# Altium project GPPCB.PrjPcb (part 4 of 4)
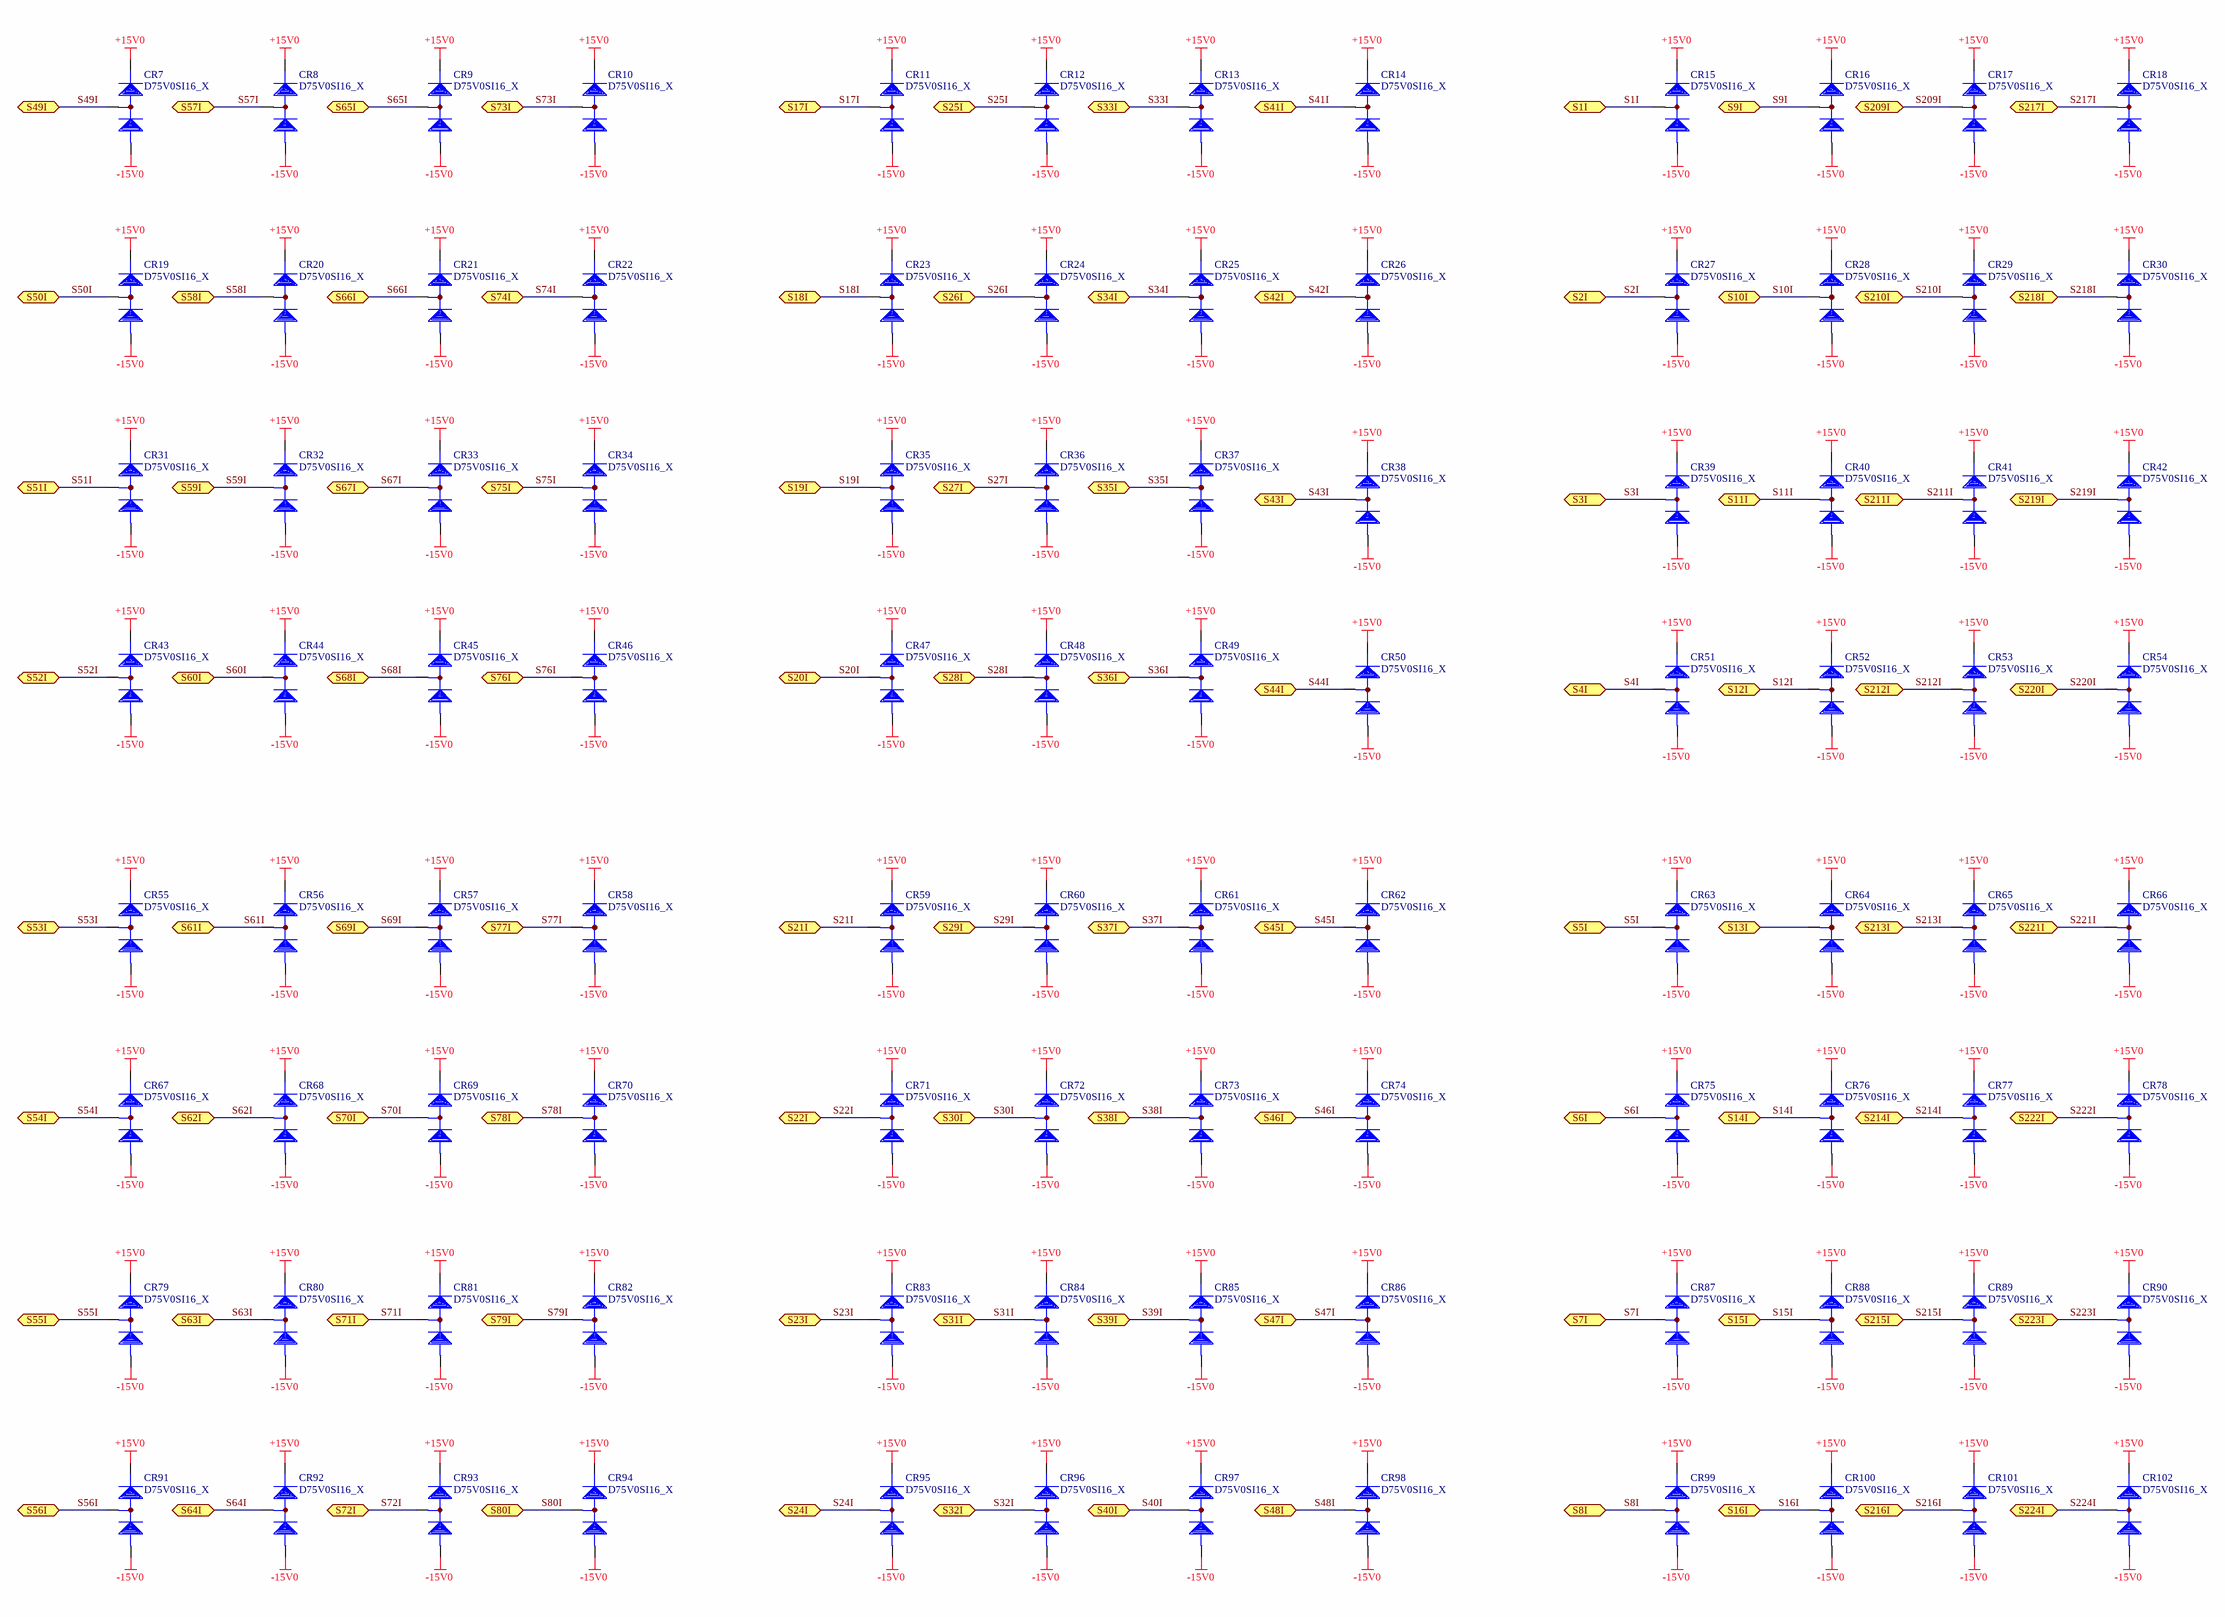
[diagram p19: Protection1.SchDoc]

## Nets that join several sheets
+5V0: 15 and 5 Volts (12 pins), ByPass (77 pins), Controller (7 pins), Decoder (9 pins), Latch1 (8 pins), Latch2 (8 pins), Latch3 (8 pins), Latch4 (8 pins), Latch5 (8 pins), Latch6 (8 pins), Latch7 (8 pins)
+15V0: 15 and 5 Volts (12 pins), Protection (128 pins), Protection1 (96 pins)
-5V0: 15 and 5 Volts (7 pins), ByPass (48 pins), Latch1 (7 pins), Latch2 (8 pins), Latch3 (8 pins), Latch4 (8 pins), Latch5 (8 pins), Latch6 (8 pins), Latch7 (8 pins)
-15V0: 15 and 5 Volts (7 pins), Protection (128 pins), Protection1 (96 pins)
DGND: 15 and 5 Volts (46 pins), 28 PowerSupply (8 pins)
GND: 28 PowerSupply (P1.3), ByPass (125 pins), Controller (15 pins), Decoder (9 pins), Latch1 (8 pins), Latch2 (8 pins), Latch3 (8 pins), Latch4 (8 pins), Latch5 (8 pins), Latch6 (8 pins), Latch7 (8 pins)
D0: Controller (U5.33), Latch1 (U16.3 U17.3 U22.3 U23.3), Latch2 (U28.3 U29.3 U34.3 U35.3), Latch3 (U40.3 U41.3 U46.3 U47.3), Latch4 (U52.3 U53.3 U58.3 U59.3), Latch5 (U64.3 U65.3 U70.3 U71.3), Latch6 (U76.3 U77.3 U82.3 U83.3), Latch7 (U88.3 U89.3 U94.3 U95.3)
D1: Controller (U5.34), Latch1 (U16.4 U17.4 U22.4 U23.4), Latch2 (U28.4 U29.4 U34.4 U35.4), Latch3 (U40.4 U41.4 U46.4 U47.4), Latch4 (U52.4 U53.4 U58.4 U59.4), Latch5 (U64.4 U65.4 U70.4 U71.4), Latch6 (U76.4 U77.4 U82.4 U83.4), Latch7 (U88.4 U89.4 U94.4 U95.4)
D2: Controller (U5.35), Latch1 (U16.7 U17.7 U22.7 U23.7), Latch2 (U28.7 U29.7 U34.7 U35.7), Latch3 (U40.7 U41.7 U46.7 U47.7), Latch4 (U52.7 U53.7 U58.7 U59.7), Latch5 (U64.7 U65.7 U70.7 U71.7), Latch6 (U76.7 U77.7 U82.7 U83.7), Latch7 (U88.7 U89.7 U94.7 U95.7)
D3: Controller (U5.36), Latch1 (U16.8 U17.8 U22.8 U23.8), Latch2 (U28.8 U29.8 U34.8 U35.8), Latch3 (U40.8 U41.8 U46.8 U47.8), Latch4 (U52.8 U53.8 U58.8 U59.8), Latch5 (U64.8 U65.8 U70.8 U71.8), Latch6 (U76.8 U77.8 U82.8 U83.8), Latch7 (U88.8 U89.8 U94.8 U95.8)
D4: Controller (U5.37), Latch1 (U16.13 U17.13 U22.13 U23.13), Latch2 (U28.13 U29.13 U34.13 U35.13), Latch3 (U40.13 U41.13 U46.13 U47.13), Latch4 (U52.13 U53.13 U58.13 U59.13), Latch5 (U64.13 U65.13 U70.13 U71.13), Latch6 (U76.13 U77.13 U82.13 U83.13), Latch7 (U88.13 U89.13 U94.13 U95.13)
D5: Controller (U5.38), Latch1 (U16.14 U17.14 U22.14 U23.14), Latch2 (U28.14 U29.14 U34.14 U35.14), Latch3 (U40.14 U41.14 U46.14 U47.14), Latch4 (U52.14 U53.14 U58.14 U59.14), Latch5 (U64.14 U65.14 U70.14 U71.14), Latch6 (U76.14 U77.14 U82.14 U83.14), Latch7 (U88.14 U89.14 U94.14 U95.14)
D6: Controller (U5.39), Latch1 (U16.17 U17.17 U22.17 U23.17), Latch2 (U28.17 U29.17 U34.17 U35.17), Latch3 (U40.17 U41.17 U46.17 U47.17), Latch4 (U52.17 U53.17 U58.17 U59.17), Latch5 (U64.17 U65.17 U70.17 U71.17), Latch6 (U76.17 U77.17 U82.17 U83.17), Latch7 (U88.17 U89.17 U94.17 U95.17)
D7: Controller (U5.40), Latch1 (U16.18 U17.18 U22.18 U23.18), Latch2 (U28.18 U29.18 U34.18 U35.18), Latch3 (U40.18 U41.18 U46.18 U47.18), Latch4 (U52.18 U53.18 U58.18 U59.18), Latch5 (U64.18 U65.18 U70.18 U71.18), Latch6 (U76.18 U77.18 U82.18 U83.18), Latch7 (U88.18 U89.18 U94.18 U95.18)
DLE1: Controller (U5.27), Decoder (8 pins)
DLE2: Controller (U5.28), Decoder (8 pins)
DLE3: Controller (U5.29), Decoder (8 pins)
LE1: Decoder (U8.15), Latch1 (U16.11)
LE2: Decoder (U8.14), Latch1 (U22.11)
LE3: Decoder (U8.13), Latch1 (U17.11)
LE4: Decoder (U8.12), Latch1 (U23.11)
LE5: Decoder (U8.11), Latch2 (U28.11)
LE6: Decoder (U8.10), Latch2 (U34.11)
LE7: Decoder (U8.9), Latch2 (U29.11)
LE8: Decoder (U8.7), Latch2 (U35.11)
LE9: Decoder (U9.15), Latch3 (U40.11)
LE10: Decoder (U9.14), Latch3 (U46.11)
LE11: Decoder (U9.13), Latch3 (U41.11)
LE12: Decoder (U9.12), Latch3 (U47.11)
LE13: Decoder (U9.11), Latch4 (U52.11)
LE14: Decoder (U9.10), Latch4 (U58.11)
LE15: Decoder (U9.9), Latch4 (U53.11)
LE16: Decoder (U9.7), Latch4 (U59.11)
LE17: Decoder (U10.15), Latch5 (U64.11)
LE18: Decoder (U10.14), Latch5 (U70.11)
LE19: Decoder (U10.13), Latch5 (U65.11)
LE20: Decoder (U10.12), Latch5 (U71.11)
LE21: Decoder (U10.11), Latch6 (U76.11)
LE22: Decoder (U10.10), Latch6 (U82.11)
LE23: Decoder (U10.9), Latch6 (U77.11)
LE24: Decoder (U10.7), Latch6 (U83.11)
LE25: Decoder (U7.15), Latch7 (U88.11)
LE26: Decoder (U7.14), Latch7 (U94.11)
LE27: Decoder (U7.13), Latch7 (U89.11)
LE28: Decoder (U7.12), Latch7 (U95.11)
LOE1: Decoder (U13.15), Latch1 (U16.1)
LOE2: Decoder (U13.14), Latch1 (U22.1)
LOE3: Decoder (U13.13), Latch1 (U17.1)
LOE4: Decoder (U13.12), Latch1 (U23.1)
LOE5: Decoder (U13.11), Latch2 (U28.1)
LOE6: Decoder (U13.10), Latch2 (U34.1)
LOE7: Decoder (U13.9), Latch2 (U29.1)
LOE8: Decoder (U13.7), Latch2 (U35.1)
LOE9: Decoder (U14.15), Latch3 (U40.1)
LOE10: Decoder (U14.14), Latch3 (U46.1)
LOE11: Decoder (U14.13), Latch3 (U41.1)
LOE12: Decoder (U14.12), Latch3 (U47.1)
LOE13: Decoder (U14.11), Latch4 (U52.1)
LOE14: Decoder (U14.10), Latch4 (U58.1)
LOE15: Decoder (U14.9), Latch4 (U53.1)
LOE16: Decoder (U14.7), Latch4 (U59.1)
LOE17: Decoder (U15.15), Latch5 (U64.1)
LOE18: Decoder (U15.14), Latch5 (U70.1)
LOE19: Decoder (U15.13), Latch5 (U65.1)
LOE20: Decoder (U15.12), Latch5 (U71.1)
LOE21: Decoder (U15.11), Latch6 (U76.1)
LOE22: Decoder (U15.10), Latch6 (U82.1)
LOE23: Decoder (U15.9), Latch6 (U77.1)
LOE24: Decoder (U15.7), Latch6 (U83.1)
LOE25: Decoder (U12.15), Latch7 (U88.1)
LOE26: Decoder (U12.14), Latch7 (U94.1)
LOE27: Decoder (U12.13), Latch7 (U89.1)
LOE28: Decoder (U12.12), Latch7 (U95.1)
S1I: Connector (J1.1), Latch1 (U27.3), Protection1 (CR15.3)
S1O: Connector (J1.17), Latch1 (U27.2)
S2I: Connector (J1.2), Latch1 (U27.14), Protection1 (CR27.3)
S2O: Connector (J1.18), Latch1 (U27.15)
S3I: Connector (J1.3), Latch1 (U27.11), Protection1 (CR39.3)
S3O: Connector (J1.19), Latch1 (U27.10)
S4I: Connector (J1.4), Latch1 (U27.6), Protection1 (CR51.3)
S4O: Connector (J1.20), Latch1 (U27.7)
S5I: Connector (J1.5), Latch1 (U19.3), Protection1 (CR63.3)
S5O: Connector (J1.21), Latch1 (U19.2)
S6I: Connector (J1.6), Latch1 (U19.14), Protection1 (CR75.3)
S6O: Connector (J1.22), Latch1 (U19.15)
S7I: Connector (J1.7), Latch1 (U19.11), Protection1 (CR87.3)
S7O: Connector (J1.23), Latch1 (U19.10)
S8I: Connector (J1.8), Latch1 (U19.6), Protection1 (CR99.3)
S8O: Connector (J1.24), Latch1 (U19.7)
S9I: Connector (J1.9), Latch1 (U21.3), Protection1 (CR16.3)
S9O: Connector (J1.25), Latch1 (U21.2)
S10I: Connector (J1.10), Latch1 (U21.14), Protection1 (CR28.3)
S10O: Connector (J1.26), Latch1 (U21.15)
S11I: Connector (J1.11), Latch1 (U21.11), Protection1 (CR40.3)
S11O: Connector (J1.27), Latch1 (U21.10)
S12I: Connector (J1.12), Latch1 (U21.6), Protection1 (CR52.3)
S12O: Connector (J1.28), Latch1 (U21.7)
S13I: Connector (J1.13), Latch1 (U25.3), Protection1 (CR64.3)
S13O: Connector (J1.29), Latch1 (U25.2)
S14I: Connector (J1.14), Latch1 (U25.14), Protection1 (CR76.3)
S14O: Connector (J1.30), Latch1 (U25.15)
S15I: Connector (J1.15), Latch1 (U25.11), Protection1 (CR88.3)
S15O: Connector (J1.31), Latch1 (U25.10)
S16I: Connector (J1.16), Latch1 (U25.6), Protection1 (CR100.3)
S16O: Connector (J1.32), Latch1 (U25.7)
S17I: Connector (J1.33), Latch2 (U30.3), Protection1 (CR11.3)
S17O: Connector (J2.6), Latch2 (U30.2)
S18I: Connector (J1.34), Latch2 (U30.14), Protection1 (CR23.3)
S18O: Connector (J2.7), Latch2 (U30.15)
S19I: Connector (J1.35), Latch2 (U30.11), Protection1 (CR35.3)
S19O: Connector (J2.8), Latch2 (U30.10)
S20I: Connector (J1.36), Latch2 (U30.6), Protection1 (CR47.3)
S20O: Connector (J2.9), Latch2 (U30.7)
S21I: Connector (J1.37), Latch2 (U32.3), Protection1 (CR59.3)
S21O: Connector (J2.10), Latch2 (U32.2)
S22I: Connector (J1.75), Latch2 (U32.14), Protection1 (CR71.3)
S22O: Connector (J2.11), Latch2 (U32.15)
S23I: Connector (J1.76), Latch2 (U32.11), Protection1 (CR83.3)
S23O: Connector (J2.12), Latch2 (U32.10)
S24I: Connector (J1.77), Latch2 (U32.6), Protection1 (CR95.3)
S24O: Connector (J2.13), Latch2 (U32.7)
S25I: Connector (J1.78), Latch2 (U36.3), Protection1 (CR12.3)
S25O: Connector (J2.14), Latch2 (U36.2)
S26I: Connector (J1.79), Latch2 (U36.14), Protection1 (CR24.3)
S26O: Connector (J2.15), Latch2 (U36.15)
S27I: Connector (J1.80), Latch2 (U36.11), Protection1 (CR36.3)
S27O: Connector (J2.16), Latch2 (U36.10)
S28I: Connector (J2.1), Latch2 (U36.6), Protection1 (CR48.3)
S28O: Connector (J2.17), Latch2 (U36.7)
S29I: Connector (J2.2), Latch2 (U38.3), Protection1 (CR60.3)
S29O: Connector (J2.18), Latch2 (U38.2)
S30I: Connector (J2.3), Latch2 (U38.14), Protection1 (CR72.3)
S30O: Connector (J2.19), Latch2 (U38.15)
S31I: Connector (J2.4), Latch2 (U38.11), Protection1 (CR84.3)
S31O: Connector (J2.20), Latch2 (U38.10)
S32I: Connector (J2.5), Latch2 (U38.6), Protection1 (CR96.3)
S32O: Connector (J2.21), Latch2 (U38.7)
S33I: Connector (J2.22), Latch2 (U31.3), Protection1 (CR13.3)
S33O: Connector (J2.75), Latch2 (U31.2)
S34I: Connector (J2.23), Latch2 (U31.14), Protection1 (CR25.3)
S34O: Connector (J2.76), Latch2 (U31.15)
S35I: Connector (J2.24), Latch2 (U31.11), Protection1 (CR37.3)
S35O: Connector (J2.77), Latch2 (U31.10)
S36I: Connector (J2.25), Latch2 (U31.6), Protection1 (CR49.3)
S36O: Connector (J2.78), Latch2 (U31.7)
S37I: Connector (J2.26), Latch2 (U33.3), Protection1 (CR61.3)
S37O: Connector (J2.79), Latch2 (U33.2)
S38I: Connector (J2.27), Latch2 (U33.14), Protection1 (CR73.3)
S38O: Connector (J2.80), Latch2 (U33.15)
S39I: Connector (J2.28), Latch2 (U33.11), Protection1 (CR85.3)
S39O: Connector (J3.1), Latch2 (U33.10)
S40I: Connector (J2.29), Latch2 (U33.6), Protection1 (CR97.3)
S40O: Connector (J3.2), Latch2 (U33.7)
S41I: Connector (J2.30), Latch2 (U37.3), Protection1 (CR14.3)
S41O: Connector (J3.3), Latch2 (U37.2)
S42I: Connector (J2.31), Latch2 (U37.14), Protection1 (CR26.3)
S42O: Connector (J3.4), Latch2 (U37.15)
S43I: Connector (J2.69), Latch2 (U37.11), Protection1 (CR38.3)
S43O: Connector (J3.5), Latch2 (U37.10)
S44I: Connector (J2.70), Latch2 (U37.6), Protection1 (CR50.3)
S44O: Connector (J3.6), Latch2 (U37.7)
S45I: Connector (J2.71), Latch2 (U39.3), Protection1 (CR62.3)
S45O: Connector (J3.7), Latch2 (U39.2)
S46I: Connector (J2.72), Latch2 (U39.14), Protection1 (CR74.3)
S46O: Connector (J3.8), Latch2 (U39.15)
S47I: Connector (J2.73), Latch2 (U39.11), Protection1 (CR86.3)
S47O: Connector (J3.9), Latch2 (U39.10)
S48I: Connector (J2.74), Latch2 (U39.6), Protection1 (CR98.3)
S48O: Connector (J3.10), Latch2 (U39.7)
S49I: Connector (J3.11), Latch3 (U42.3), Protection1 (CR7.3)
S49O: Connector (J3.64), Latch3 (U42.2)
S50I: Connector (J3.12), Latch3 (U42.14), Protection1 (CR19.3)
S50O: Connector (J3.65), Latch3 (U42.15)
S51I: Connector (J3.13), Latch3 (U42.11), Protection1 (CR31.3)
S51O: Connector (J3.66), Latch3 (U42.10)
S52I: Connector (J3.14), Latch3 (U42.6), Protection1 (CR43.3)
S52O: Connector (J3.67), Latch3 (U42.7)
S53I: Connector (J3.15), Latch3 (U44.3), Protection1 (CR55.3)
S53O: Connector (J3.68), Latch3 (U44.2)
S54I: Connector (J3.16), Latch3 (U44.14), Protection1 (CR67.3)
S54O: Connector (J3.69), Latch3 (U44.15)
S55I: Connector (J3.17), Latch3 (U44.11), Protection1 (CR79.3)
S55O: Connector (J3.70), Latch3 (U44.10)
S56I: Connector (J3.18), Latch3 (U44.6), Protection1 (CR91.3)
S56O: Connector (J3.71), Latch3 (U44.7)
S57I: Connector (J3.19), Latch3 (U48.3), Protection1 (CR8.3)
S57O: Connector (J3.72), Latch3 (U48.2)
S58I: Connector (J3.20), Latch3 (U48.14), Protection1 (CR20.3)
S58O: Connector (J3.73), Latch3 (U48.15)
S59I: Connector (J3.21), Latch3 (U48.11), Protection1 (CR32.3)
S59O: Connector (J3.74), Latch3 (U48.10)
S60I: Connector (J3.22), Latch3 (U48.6), Protection1 (CR44.3)
S60O: Connector (J3.75), Latch3 (U48.7)
S61I: Connector (J3.23), Latch3 (U50.3), Protection1 (CR56.3)
S61O: Connector (J3.76), Latch3 (U50.2)
S62I: Connector (J3.24), Latch3 (U50.14), Protection1 (CR68.3)
S62O: Connector (J3.77), Latch3 (U50.15)
S63I: Connector (J3.25), Latch3 (U50.11), Protection1 (CR80.3)
S63O: Connector (J3.78), Latch3 (U50.10)
S64I: Connector (J3.63), Latch3 (U50.6), Protection1 (CR92.3)
S64O: Connector (J3.79), Latch3 (U50.7)
S65I: Connector (J3.80), Latch3 (U43.3), Protection1 (CR9.3)
S65O: Connector (J4.16), Latch3 (U43.2)
S66I: Connector (J4.1), Latch3 (U43.14), Protection1 (CR21.3)
S66O: Connector (J4.17), Latch3 (U43.15)
S67I: Connector (J4.2), Latch3 (U43.11), Protection1 (CR33.3)
S67O: Connector (J4.18), Latch3 (U43.10)
S68I: Connector (J4.3), Latch3 (U43.6), Protection1 (CR45.3)
S68O: Connector (J4.19), Latch3 (U43.7)
S69I: Connector (J4.4), Latch3 (U45.3), Protection1 (CR57.3)
S69O: Connector (J4.57), Latch3 (U45.2)
S70I: Connector (J4.5), Latch3 (U45.14), Protection1 (CR69.3)
S70O: Connector (J4.58), Latch3 (U45.15)
S71I: Connector (J4.6), Latch3 (U45.11), Protection1 (CR81.3)
S71O: Connector (J4.59), Latch3 (U45.10)
S72I: Connector (J4.7), Latch3 (U45.6), Protection1 (CR93.3)
S72O: Connector (J4.60), Latch3 (U45.7)
S73I: Connector (J4.8), Latch3 (U49.3), Protection1 (CR10.3)
S73O: Connector (J4.61), Latch3 (U49.2)
S74I: Connector (J4.9), Latch3 (U49.14), Protection1 (CR22.3)
S74O: Connector (J4.62), Latch3 (U49.15)
S75I: Connector (J4.10), Latch3 (U49.11), Protection1 (CR34.3)
S75O: Connector (J4.63), Latch3 (U49.10)
S76I: Connector (J4.11), Latch3 (U49.6), Protection1 (CR46.3)
S76O: Connector (J4.64), Latch3 (U49.7)
S77I: Connector (J4.12), Latch3 (U51.3), Protection1 (CR58.3)
S77O: Connector (J4.65), Latch3 (U51.2)
S78I: Connector (J4.13), Latch3 (U51.14), Protection1 (CR70.3)
S78O: Connector (J4.66), Latch3 (U51.15)
S79I: Connector (J4.14), Latch3 (U51.11), Protection1 (CR82.3)
S79O: Connector (J4.67), Latch3 (U51.10)
S80I: Connector (J4.15), Latch3 (U51.6), Protection1 (CR94.3)
S80O: Connector (J4.68), Latch3 (U51.7)
S81I: Connector (J4.69), Latch4 (U54.3), Protection (CR199.3)
S81O: Connector (J5.5), Latch4 (U54.2)
S82I: Connector (J4.70), Latch4 (U54.14), Protection (CR215.3)
S82O: Connector (J5.6), Latch4 (U54.15)
S83I: Connector (J4.71), Latch4 (U54.11), Protection (CR200.3)
S83O: Connector (J5.7), Latch4 (U54.10)
S84I: Connector (J4.72), Latch4 (U54.6), Protection (CR216.3)
S84O: Connector (J5.8), Latch4 (U54.7)
S85I: Connector (J4.73), Latch4 (U56.3), Protection (CR201.3)
S85O: Connector (J5.9), Latch4 (U56.2)
S86I: Connector (J4.74), Latch4 (U56.14), Protection (CR217.3)
S86O: Connector (J5.10), Latch4 (U56.15)
S87I: Connector (J4.75), Latch4 (U56.11), Protection (CR202.3)
S87O: Connector (J5.11), Latch4 (U56.10)
S88I: Connector (J4.76), Latch4 (U56.6), Protection (CR218.3)
S88O: Connector (J5.12), Latch4 (U56.7)
S89I: Connector (J4.77), Latch4 (U60.3), Protection (CR203.3)
S89O: Connector (J5.13), Latch4 (U60.2)
S90I: Connector (J4.78), Latch4 (U60.14), Protection (CR219.3)
S90O: Connector (J5.51), Latch4 (U60.15)
S91I: Connector (J4.79), Latch4 (U60.11), Protection (CR204.3)
S91O: Connector (J5.52), Latch4 (U60.10)
S92I: Connector (J4.80), Latch4 (U60.6), Protection (CR220.3)
S92O: Connector (J5.53), Latch4 (U60.7)
S93I: Connector (J5.1), Latch4 (U62.3), Protection (CR205.3)
S93O: Connector (J5.54), Latch4 (U62.2)
S94I: Connector (J5.2), Latch4 (U62.14), Protection (CR221.3)
S94O: Connector (J5.55), Latch4 (U62.15)
S95I: Connector (J5.3), Latch4 (U62.11), Protection (CR206.3)
S95O: Connector (J5.56), Latch4 (U62.10)
S96I: Connector (J5.4), Latch4 (U62.6), Protection (CR222.3)
S96O: Connector (J5.57), Latch4 (U62.7)
S97I: Connector (J5.58), Latch4 (U55.3), Protection (CR207.3)
S97O: Connector (J5.74), Latch4 (U55.2)
S98I: Connector (J5.59), Latch4 (U55.14), Protection (CR223.3)
S98O: Connector (J5.75), Latch4 (U55.15)
S99I: Connector (J5.60), Latch4 (U55.11), Protection (CR208.3)
S99O: Connector (J5.76), Latch4 (U55.10)
S100I: Connector (J5.61), Latch4 (U55.6), Protection (CR224.3)
S100O: Connector (J5.77), Latch4 (U55.7)
S101I: Connector (J5.62), Latch4 (U57.3), Protection (CR209.3)
S101O: Connector (J5.78), Latch4 (U57.2)
S102I: Connector (J5.63), Latch4 (U57.14), Protection (CR225.3)
S102O: Connector (J5.79), Latch4 (U57.15)
S103I: Connector (J5.64), Latch4 (U57.11), Protection (CR210.3)
S103O: Connector (J5.80), Latch4 (U57.10)
S104I: Connector (J5.65), Latch4 (U57.6), Protection (CR226.3)
S104O: Connector (J6.1), Latch4 (U57.7)
S105I: Connector (J5.66), Latch4 (U61.3), Protection (CR211.3)
S105O: Connector (J6.2), Latch4 (U61.2)
S106I: Connector (J5.67), Latch4 (U61.14), Protection (CR227.3)
S106O: Connector (J6.3), Latch4 (U61.15)
S107I: Connector (J5.68), Latch4 (U61.11), Protection (CR212.3)
S107O: Connector (J6.4), Latch4 (U61.10)
S108I: Connector (J5.69), Latch4 (U61.6), Protection (CR228.3)
S108O: Connector (J6.5), Latch4 (U61.7)
S109I: Connector (J5.70), Latch4 (U63.3), Protection (CR213.3)
S109O: Connector (J6.6), Latch4 (U63.2)
S110I: Connector (J5.71), Latch4 (U63.14), Protection (CR229.3)
S110O: Connector (J6.7), Latch4 (U63.15)
S111I: Connector (J5.72), Latch4 (U63.11), Protection (CR214.3)
S111O: Connector (J1.38), Latch4 (U63.10)
S112I: Connector (J5.73), Latch4 (U63.6), Protection (CR230.3)
S112O: Connector (J1.39), Latch4 (U63.7)
S113I: Connector (J1.40), Latch5 (U66.3), Protection (CR167.3)
S113O: Connector (J1.56), Latch5 (U66.2)
S114I: Connector (J1.41), Latch5 (U66.14), Protection (CR183.3)
S114O: Connector (J1.57), Latch5 (U66.15)
S115I: Connector (J1.42), Latch5 (U66.11), Protection (CR168.3)
S115O: Connector (J1.58), Latch5 (U66.10)
S116I: Connector (J1.43), Latch5 (U66.6), Protection (CR184.3)
S116O: Connector (J1.59), Latch5 (U66.7)
S117I: Connector (J1.44), Latch5 (U68.3), Protection (CR169.3)
S117O: Connector (J1.60), Latch5 (U68.2)
S118I: Connector (J1.45), Latch5 (U68.14), Protection (CR185.3)
S118O: Connector (J1.61), Latch5 (U68.15)
S119I: Connector (J1.46), Latch5 (U68.11), Protection (CR170.3)
S119O: Connector (J1.62), Latch5 (U68.10)
S120I: Connector (J1.47), Latch5 (U68.6), Protection (CR186.3)
S120O: Connector (J1.63), Latch5 (U68.7)
S121I: Connector (J1.48), Latch5 (U72.3), Protection (CR171.3)
S121O: Connector (J1.64), Latch5 (U72.2)
S122I: Connector (J1.49), Latch5 (U72.14), Protection (CR187.3)
S122O: Connector (J1.65), Latch5 (U72.15)
S123I: Connector (J1.50), Latch5 (U72.11), Protection (CR172.3)
S123O: Connector (J1.66), Latch5 (U72.10)
S124I: Connector (J1.51), Latch5 (U72.6), Protection (CR188.3)
S124O: Connector (J1.67), Latch5 (U72.7)
S125I: Connector (J1.52), Latch5 (U74.3), Protection (CR173.3)
S125O: Connector (J1.68), Latch5 (U74.2)
S126I: Connector (J1.53), Latch5 (U74.14), Protection (CR189.3)
S126O: Connector (J1.69), Latch5 (U74.15)
S127I: Connector (J1.54), Latch5 (U74.11), Protection (CR174.3)
S127O: Connector (J1.70), Latch5 (U74.10)
S128I: Connector (J1.55), Latch5 (U74.6), Protection (CR190.3)
S128O: Connector (J1.71), Latch5 (U74.7)
S129I: Connector (J1.72), Latch5 (U67.3), Protection (CR175.3)
S129O: Connector (J2.45), Latch5 (U67.2)
S130I: Connector (J1.73), Latch5 (U67.14), Protection (CR191.3)
S130O: Connector (J2.46), Latch5 (U67.15)
S131I: Connector (J1.74), Latch5 (U67.11), Protection (CR176.3)
S131O: Connector (J2.47), Latch5 (U67.10)
S132I: Connector (J2.32), Latch5 (U67.6), Protection (CR192.3)
S132O: Connector (J2.48), Latch5 (U67.7)
S133I: Connector (J2.33), Latch5 (U69.3), Protection (CR177.3)
S133O: Connector (J2.49), Latch5 (U69.2)
S134I: Connector (J2.34), Latch5 (U69.14), Protection (CR193.3)
S134O: Connector (J2.50), Latch5 (U69.15)
S135I: Connector (J2.35), Latch5 (U69.11), Protection (CR178.3)
S135O: Connector (J2.51), Latch5 (U69.10)
S136I: Connector (J2.36), Latch5 (U69.6), Protection (CR194.3)
S136O: Connector (J2.52), Latch5 (U69.7)
S137I: Connector (J2.37), Latch5 (U73.3), Protection (CR179.3)
S137O: Connector (J2.53), Latch5 (U73.2)
S138I: Connector (J2.38), Latch5 (U73.14), Protection (CR195.3)
S138O: Connector (J2.54), Latch5 (U73.15)
S139I: Connector (J2.39), Latch5 (U73.11), Protection (CR180.3)
S139O: Connector (J2.55), Latch5 (U73.10)
S140I: Connector (J2.40), Latch5 (U73.6), Protection (CR196.3)
S140O: Connector (J2.56), Latch5 (U73.7)
S141I: Connector (J2.41), Latch5 (U75.3), Protection (CR181.3)
S141O: Connector (J2.57), Latch5 (U75.2)
S142I: Connector (J2.42), Latch5 (U75.14), Protection (CR197.3)
S142O: Connector (J2.58), Latch5 (U75.15)
S143I: Connector (J2.43), Latch5 (U75.11), Protection (CR182.3)
S143O: Connector (J2.59), Latch5 (U75.10)
S144I: Connector (J2.44), Latch5 (U75.6), Protection (CR198.3)
S144O: Connector (J2.60), Latch5 (U75.7)
S145I: Connector (J2.61), Latch6 (U78.3), Protection (CR135.3)
S145O: Connector (J3.34), Latch6 (U78.2)
S146I: Connector (J2.62), Latch6 (U78.14), Protection (CR151.3)
S146O: Connector (J3.35), Latch6 (U78.15)
S147I: Connector (J2.63), Latch6 (U78.11), Protection (CR136.3)
S147O: Connector (J3.36), Latch6 (U78.10)
S148I: Connector (J2.64), Latch6 (U78.6), Protection (CR152.3)
S148O: Connector (J3.37), Latch6 (U78.7)
S149I: Connector (J2.65), Latch6 (U80.3), Protection (CR137.3)
S149O: Connector (J3.38), Latch6 (U80.2)
S150I: Connector (J2.66), Latch6 (U80.14), Protection (CR153.3)
S150O: Connector (J3.39), Latch6 (U80.15)
S151I: Connector (J2.67), Latch6 (U80.11), Protection (CR138.3)
S151O: Connector (J3.40), Latch6 (U80.10)
S152I: Connector (J2.68), Latch6 (U80.6), Protection (CR154.3)
S152O: Connector (J3.41), Latch6 (U80.7)
S153I: Connector (J3.26), Latch6 (U84.3), Protection (CR139.3)
S153O: Connector (J3.42), Latch6 (U84.2)
S154I: Connector (J3.27), Latch6 (U84.14), Protection (CR155.3)
S154O: Connector (J3.43), Latch6 (U84.15)
S155I: Connector (J3.28), Latch6 (U84.11), Protection (CR140.3)
S155O: Connector (J3.44), Latch6 (U84.10)
S156I: Connector (J3.29), Latch6 (U84.6), Protection (CR156.3)
S156O: Connector (J3.45), Latch6 (U84.7)
S157I: Connector (J3.30), Latch6 (U86.3), Protection (CR141.3)
S157O: Connector (J3.46), Latch6 (U86.2)
S158I: Connector (J3.31), Latch6 (U86.14), Protection (CR157.3)
S158O: Connector (J3.47), Latch6 (U86.15)
S159I: Connector (J3.32), Latch6 (U86.11), Protection (CR142.3)
S159O: Connector (J3.48), Latch6 (U86.10)
S160I: Connector (J3.33), Latch6 (U86.6), Protection (CR158.3)
S160O: Connector (J3.49), Latch6 (U86.7)
S161I: Connector (J3.50), Latch6 (U79.3), Protection (CR143.3)
S161O: Connector (J4.23), Latch6 (U79.2)
S162I: Connector (J3.51), Latch6 (U79.14), Protection (CR159.3)
S162O: Connector (J4.24), Latch6 (U79.15)
S163I: Connector (J3.52), Latch6 (U79.11), Protection (CR144.3)
S163O: Connector (J4.25), Latch6 (U79.10)
S164I: Connector (J3.53), Latch6 (U79.6), Protection (CR160.3)
S164O: Connector (J4.26), Latch6 (U79.7)
S165I: Connector (J3.54), Latch6 (U81.3), Protection (CR145.3)
S165O: Connector (J4.27), Latch6 (U81.2)
S166I: Connector (J3.55), Latch6 (U81.14), Protection (CR161.3)
S166O: Connector (J4.28), Latch6 (U81.15)
S167I: Connector (J3.56), Latch6 (U81.11), Protection (CR146.3)
S167O: Connector (J4.29), Latch6 (U81.10)
S168I: Connector (J3.57), Latch6 (U81.6), Protection (CR162.3)
S168O: Connector (J4.30), Latch6 (U81.7)
S169I: Connector (J3.58), Latch6 (U85.3), Protection (CR147.3)
S169O: Connector (J4.31), Latch6 (U85.2)
S170I: Connector (J3.59), Latch6 (U85.14), Protection (CR163.3)
S170O: Connector (J4.32), Latch6 (U85.15)
S171I: Connector (J3.60), Latch6 (U85.11), Protection (CR148.3)
S171O: Connector (J4.33), Latch6 (U85.10)
S172I: Connector (J3.61), Latch6 (U85.6), Protection (CR164.3)
S172O: Connector (J4.34), Latch6 (U85.7)
S173I: Connector (J3.62), Latch6 (U87.3), Protection (CR149.3)
S173O: Connector (J4.35), Latch6 (U87.2)
S174I: Connector (J4.20), Latch6 (U87.14), Protection (CR165.3)
S174O: Connector (J4.36), Latch6 (U87.15)
S175I: Connector (J4.21), Latch6 (U87.11), Protection (CR150.3)
S175O: Connector (J4.37), Latch6 (U87.10)
S176I: Connector (J4.22), Latch6 (U87.6), Protection (CR166.3)
S176O: Connector (J4.38), Latch6 (U87.7)
S177I: Connector (J4.39), Latch7 (U90.3), Protection (CR103.3)
S177O: Connector (J4.55), Latch7 (U90.2)
S178I: Connector (J4.40), Latch7 (U90.14), Protection (CR119.3)
S178O: Connector (J4.56), Latch7 (U90.15)
S179I: Connector (J4.41), Latch7 (U90.11), Protection (CR104.3)
S179O: Connector (J5.14), Latch7 (U90.10)
S180I: Connector (J4.42), Latch7 (U90.6), Protection (CR120.3)
S180O: Connector (J5.15), Latch7 (U90.7)
S181I: Connector (J4.43), Latch7 (U92.3), Protection (CR105.3)
S181O: Connector (J5.16), Latch7 (U92.2)
S182I: Connector (J4.44), Latch7 (U92.14), Protection (CR121.3)
S182O: Connector (J5.17), Latch7 (U92.15)
S183I: Connector (J4.45), Latch7 (U92.11), Protection (CR106.3)
S183O: Connector (J5.18), Latch7 (U92.10)
S184I: Connector (J4.46), Latch7 (U92.6), Protection (CR122.3)
S184O: Connector (J5.19), Latch7 (U92.7)
S185I: Connector (J4.47), Latch7 (U96.3), Protection (CR107.3)
S185O: Connector (J5.20), Latch7 (U96.2)
S186I: Connector (J4.48), Latch7 (U96.14), Protection (CR123.3)
S186O: Connector (J5.21), Latch7 (U96.15)
S187I: Connector (J4.49), Latch7 (U96.11), Protection (CR108.3)
S187O: Connector (J5.22), Latch7 (U96.10)
S188I: Connector (J4.50), Latch7 (U96.6), Protection (CR124.3)
S188O: Connector (J5.23), Latch7 (U96.7)
S189I: Connector (J4.51), Latch7 (U98.3), Protection (CR109.3)
S189O: Connector (J5.24), Latch7 (U98.2)
S190I: Connector (J4.52), Latch7 (U98.14), Protection (CR125.3)
S190O: Connector (J5.25), Latch7 (U98.15)
S191I: Connector (J4.53), Latch7 (U98.11), Protection (CR110.3)
S191O: Connector (J5.26), Latch7 (U98.10)
S192I: Connector (J4.54), Latch7 (U98.6), Protection (CR126.3)
S192O: Connector (J5.27), Latch7 (U98.7)
S193I: Connector (J5.28), Latch7 (U91.3), Protection (CR111.3)
S193O: Connector (J5.44), Latch7 (U91.2)
S194I: Connector (J5.29), Latch7 (U91.14), Protection (CR127.3)
S194O: Connector (J5.45), Latch7 (U91.15)
S195I: Connector (J5.30), Latch7 (U91.11), Protection (CR112.3)
S195O: Connector (J5.46), Latch7 (U91.10)
S196I: Connector (J5.31), Latch7 (U91.6), Protection (CR128.3)
S196O: Connector (J5.47), Latch7 (U91.7)
S197I: Connector (J5.32), Latch7 (U93.3), Protection (CR113.3)
S197O: Connector (J5.48), Latch7 (U93.2)
S198I: Connector (J5.33), Latch7 (U93.14), Protection (CR129.3)
S198O: Connector (J5.49), Latch7 (U93.15)
S199I: Connector (J5.34), Latch7 (U93.11), Protection (CR114.3)
S199O: Connector (J5.50), Latch7 (U93.10)
S200I: Connector (J5.35), Latch7 (U93.6), Protection (CR130.3)
S200O: Connector (J6.8), Latch7 (U93.7)
S201I: Connector (J5.36), Latch7 (U97.3), Protection (CR115.3)
S201O: Connector (J6.9), Latch7 (U97.2)
S202I: Connector (J5.37), Latch7 (U97.14), Protection (CR131.3)
S202O: Connector (J6.10), Latch7 (U97.15)
S203I: Connector (J5.38), Latch7 (U97.11), Protection (CR116.3)
S203O: Connector (J6.11), Latch7 (U97.10)
S204I: Connector (J5.39), Latch7 (U97.6), Protection (CR132.3)
S204O: Connector (J6.12), Latch7 (U97.7)
S205I: Connector (J5.40), Latch7 (U99.3), Protection (CR117.3)
S205O: Connector (J6.13), Latch7 (U99.2)
S206I: Connector (J5.41), Latch7 (U99.14), Protection (CR133.3)
S206O: Connector (J6.14), Latch7 (U99.15)
S207I: Connector (J5.42), Latch7 (U99.11), Protection (CR118.3)
S207O: Connector (J6.15), Latch7 (U99.10)
S208I: Connector (J5.43), Latch7 (U99.6), Protection (CR134.3)
S208O: Connector (J6.16), Latch7 (U99.7)
S209I: Connector (J6.17), Latch1 (U18.3), Protection1 (CR17.3)
S209O: Connector (J6.33), Latch1 (U18.2)
S210I: Connector (J6.18), Latch1 (U18.14), Protection1 (CR29.3)
S210O: Connector (J6.34), Latch1 (U18.15)
S211I: Connector (J6.19), Latch1 (U18.11), Protection1 (CR41.3)
S211O: Connector (J6.35), Latch1 (U18.10)
S212I: Connector (J6.20), Latch1 (U18.6), Protection1 (CR53.3)
S212O: Connector (J6.36), Latch1 (U18.7)
S213I: Connector (J6.21), Latch1 (U20.3), Protection1 (CR65.3)
S213O: Connector (J6.37), Latch1 (U20.2)
S214I: Connector (J6.22), Latch1 (U20.14), Protection1 (CR77.3)
S214O: Connector (J6.38), Latch1 (U20.15)
S215I: Connector (J6.23), Latch1 (U20.11), Protection1 (CR89.3)
S215O: Connector (J6.39), Latch1 (U20.10)
S216I: Connector (J6.24), Latch1 (U20.6), Protection1 (CR101.3)
S216O: Connector (J6.40), Latch1 (U20.7)
S217I: Connector (J6.25), Latch1 (U24.3), Protection1 (CR18.3)
S217O: Connector (J6.41), Latch1 (U24.2)
S218I: Connector (J6.26), Latch1 (U24.14), Protection1 (CR30.3)
S218O: Connector (J6.42), Latch1 (U24.15)
S219I: Connector (J6.27), Latch1 (U24.11), Protection1 (CR42.3)
S219O: Connector (J6.43), Latch1 (U24.10)
S220I: Connector (J6.28), Latch1 (U24.6), Protection1 (CR54.3)
S220O: Connector (J6.44), Latch1 (U24.7)
S221I: Connector (J6.29), Latch1 (U26.3), Protection1 (CR66.3)
S221O: Connector (J6.45), Latch1 (U26.2)
S222I: Connector (J6.30), Latch1 (U26.14), Protection1 (CR78.3)
S222O: Connector (J6.46), Latch1 (U26.15)
S223I: Connector (J6.31), Latch1 (U26.11), Protection1 (CR90.3)
S223O: Connector (J6.47), Latch1 (U26.10)
S224I: Connector (J6.32), Latch1 (U26.6), Protection1 (CR102.3)
S224O: Connector (J6.48), Latch1 (U26.7)
SLT1: Controller (U5.20), Decoder (8 pins)
SLT2: Controller (U5.21), Decoder (8 pins)
SLT3: Controller (U5.22), Decoder (8 pins)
